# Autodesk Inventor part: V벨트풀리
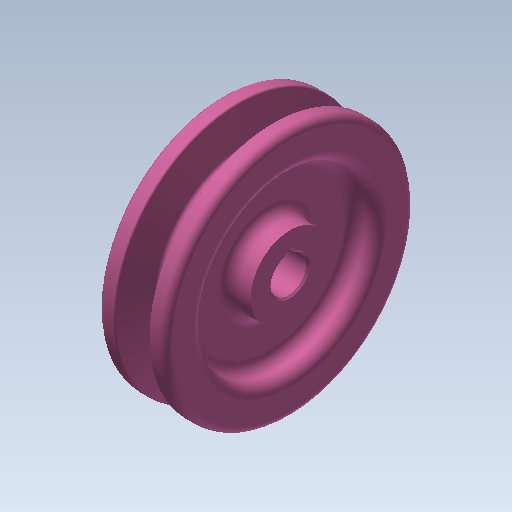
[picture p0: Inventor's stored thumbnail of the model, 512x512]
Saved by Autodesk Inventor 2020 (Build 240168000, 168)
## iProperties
Created: 2015-11
Part Number: V벨트풀리
Material: 강철, 탄소
Document SubType Name: Modeling
Designer: mduedu
Density: 1 g/cm^3
Appearance: 분홍색
Author: mduedu
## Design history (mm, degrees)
sketch "스케치1"
  geometry: L1 (-9.5, 0)-(9.5, 0); L2 (0, 0)-(0, 34.7); L3 (-4.825, 34.7)-(-9.5, 34.7); L4 (-9.5, 34.7)-(-9.5, 0); L5 (0, 25.7)-(-2.074, 25.7); L6 (-2.074, 25.7)-(-4.825, 34.7); L7 (4.825, 34.7)-(9.5, 34.7); L8 (9.5, 34.7)-(9.5, 0); L9 (0, 25.7)-(2.074, 25.7); L10 (2.074, 25.7)-(4.825, 34.7); L11 (-9.5, 32)-(9.5, 32); 3 further points
  constraints: 22 end point, 7 point on line, 4 perpendicular, 3 symmetric about line, 1 coincident, 1 horizontal, 1 horizontal alignment, 1 midpoint, 1 vertical
  dimensions: "d0" = 19 distance of L1.start L1.end; "d2" = 69.4 diameter of L2.end L1 (derived); "d3" = 34 deg angle of L10 L6; "d4" = 6.3 distance between parallel lines of L11 L9; "d5" = 2.7 distance between parallel lines of L7 L11; "d6" = 8 distance of point (4, 32) point (-4, 32); "d7" = 64 diameter of L11 L1
revolve "회전1" sketch "스케치1" stored, may be unused: angle "d8" = 90 deg
sketch "스케치2"
  geometry: C1 r 24 at (0, 0); C2 r 11 at (0, 0); 1 further point
  constraints: 2 centre point, 2 coincident
  dimensions: "d9" = 48 diameter of C1; "d10" = 22 diameter of C2
extrude "돌출1" cut sketch "스케치2" distance "d11" = 6; taper "d12" = 0 deg
fillet "모깎기1" dims "d13" = 3
fillet "모깎기2" dims "d14" = 3
fillet "모깎기3" dims "d15" = 1, "d16" = 0.5, "d17" = 2
hole "구멍1" diameter "d20" = 10; stored, may be unused: countersink angle "d24" = 90 deg, drill point angle "d26" = 118 deg; dims "d18" = 10, "d19" = 10, "d21" = 6, "d22" = 4, "d23" = 2, "d25" = 8
sketch "스케치3"
  geometry: L1 (-1.5, 0)-(1.5, 0); L2 (1.5, 0)-(1.5, 6.4); L3 (1.5, 6.4)-(-1.5, 6.4); L4 (-1.5, 6.4)-(-1.5, 0); 2 further points
  constraints: 8 end point, 2 parallel, 1 coincident, 1 horizontal, 1 midpoint, 1 perpendicular
  dimensions: "d27" = 3 distance of L2.end L3.end; "d29" = 6.4 distance of L3.end L1.start
extrude "돌출2" cut sketch "스케치3" extent not by distance; stored distance "d30" = 6; taper "d31" = 0 deg
chamfer "모따기1" distance "d32" = 0.5; stored, may be unused: second distance "d33" = 2, angle "d34" = 45 deg
node "솔리드1"
mirror "대칭1"
